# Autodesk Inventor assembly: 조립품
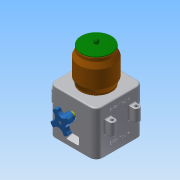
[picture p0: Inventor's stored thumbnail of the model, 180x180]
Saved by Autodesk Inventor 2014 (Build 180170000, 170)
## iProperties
Created: 2018-01
Part Number: 조립품
Document SubType Name: Assembly
Designer: Administrator
Author: Administrator
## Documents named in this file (9)
- C:\Users\Administrator\Desktop\480107V1044\조립품.iam
- C:\Users\Administrator\Desktop\480107V1044\본체.ipt
- C:\Users\Administrator\Desktop\480107V1044\본체커버.ipt
- C:\Users\Administrator\Desktop\480107V1044\볼트 M3x12.ipt
- C:\Users\Administrator\Desktop\480107V1044\볼트 M4x12.ipt
- C:\Users\Administrator\Desktop\480107V1044\용기.ipt
- C:\Users\Administrator\Desktop\480107V1044\용기캡.ipt
- C:\Users\Administrator\Desktop\480107V1044\핸들.ipt
- C:\Users\Administrator\Desktop\480107V1044\핸들축.ipt
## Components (2 placed, 2 different names)
1. 핸들:1
2. 핸들축:1
